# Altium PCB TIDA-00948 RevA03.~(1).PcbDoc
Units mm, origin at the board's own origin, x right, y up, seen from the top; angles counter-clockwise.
Board outline 125.73 x 87.63 mm, 2 copper layers (Top Layer, Bottom Layer), stack 1.575 mm thick; 28 components, 8 nets, 44 pads, 0 vias.
Unrouted connection lines stored in the file: 1.
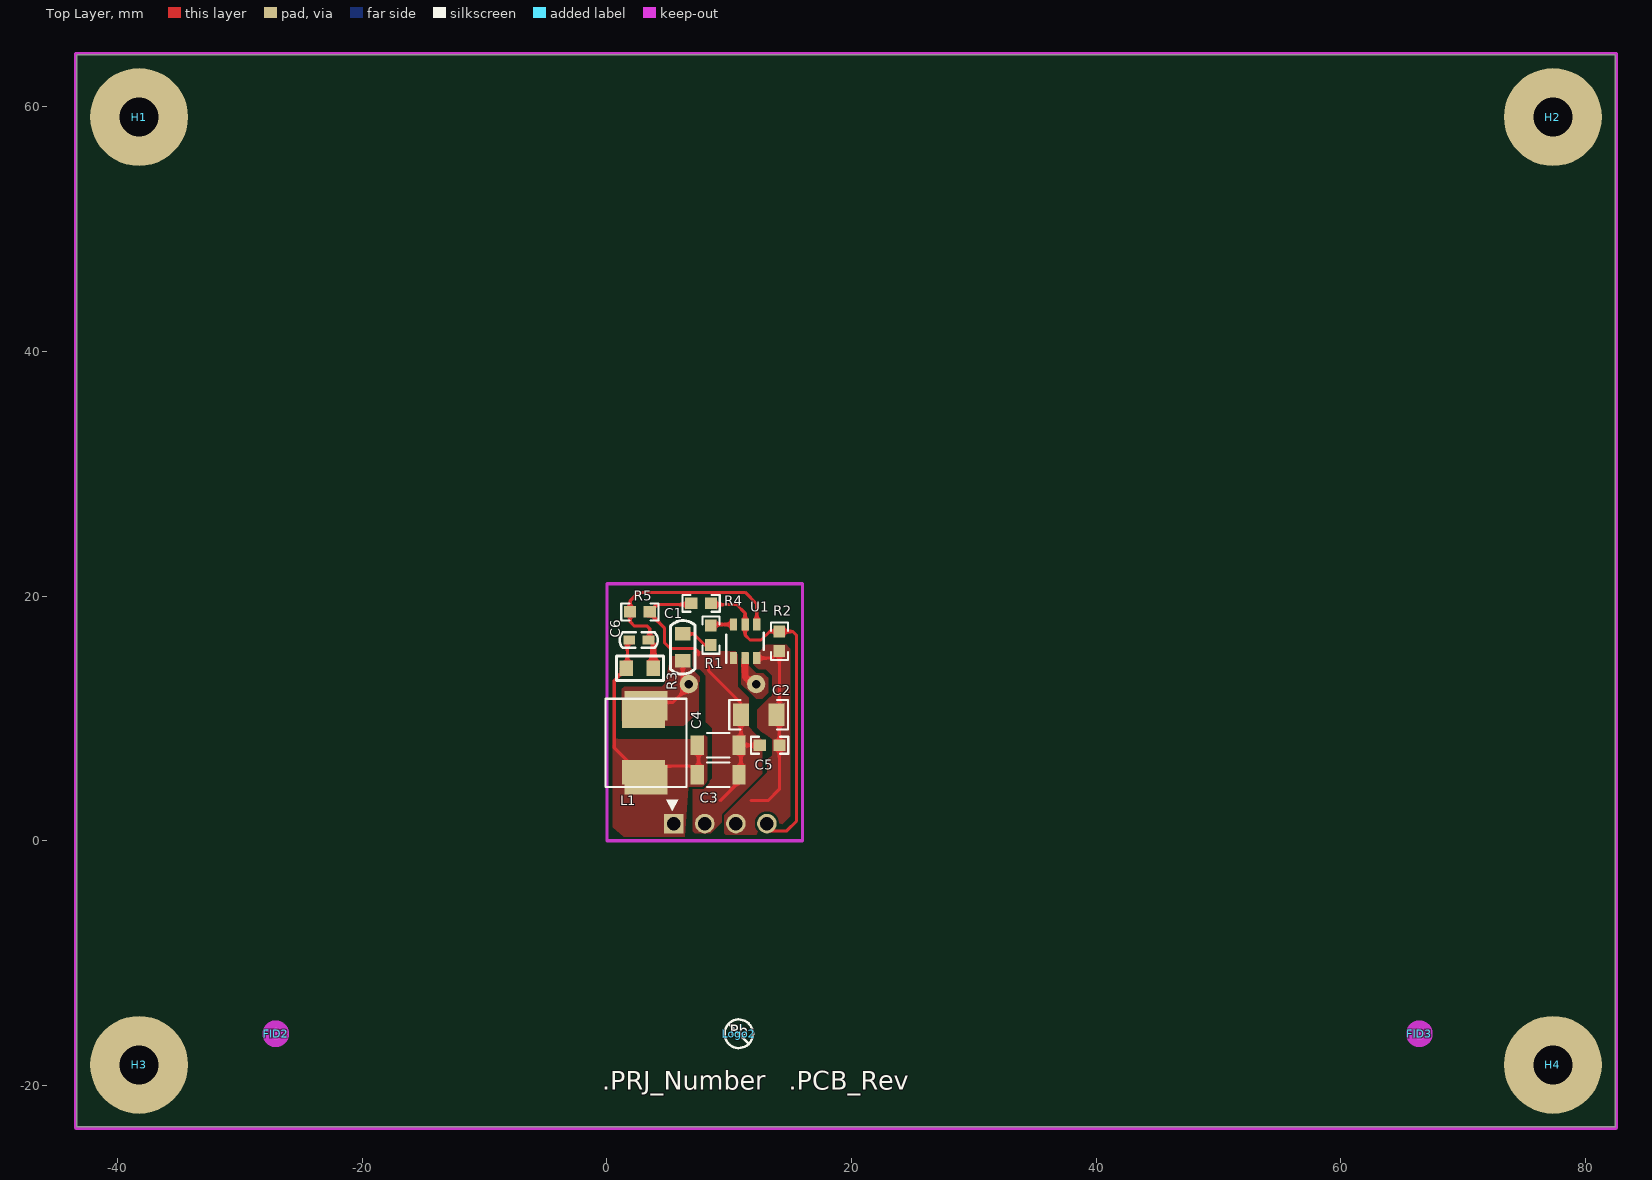
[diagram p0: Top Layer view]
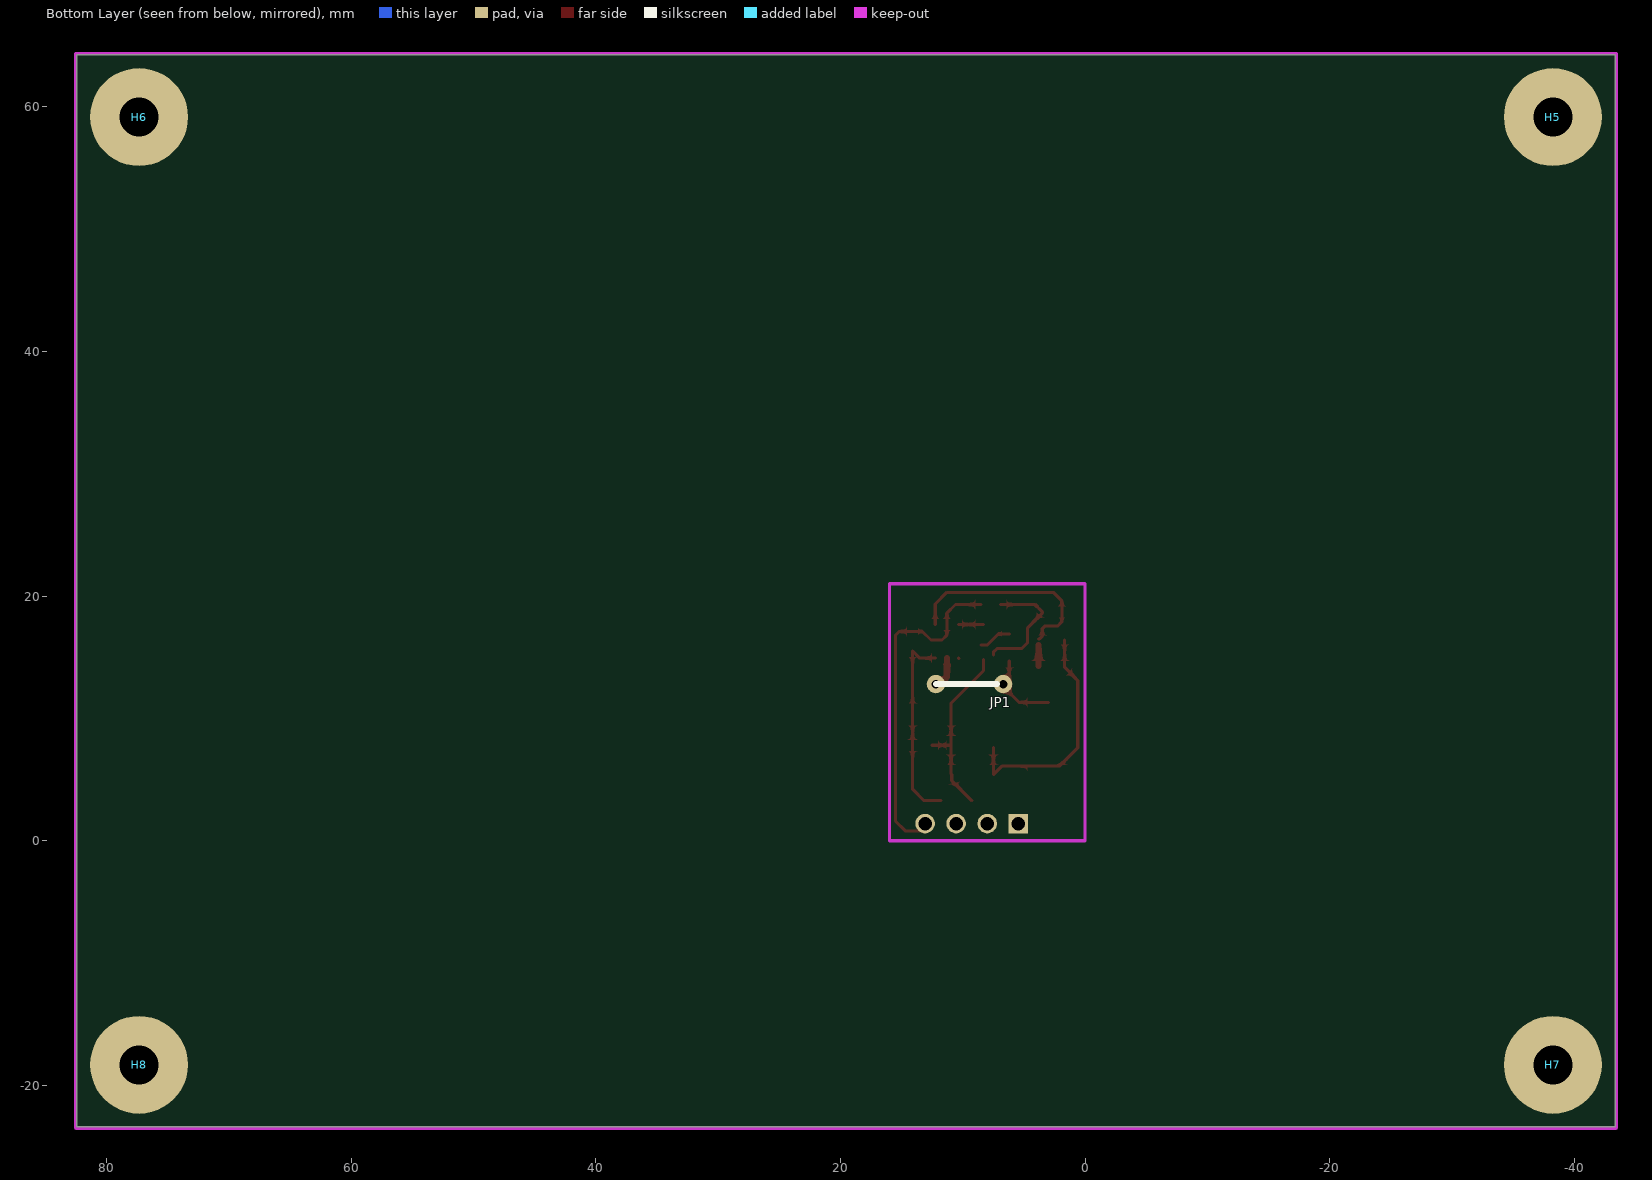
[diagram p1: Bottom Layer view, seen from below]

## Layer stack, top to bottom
Top Solder: solder mask 0.0102, Solder Resist, Dk 3.5
Top Layer: signal copper 0.0356
Dielectric1: core 1.5037, FR-4, Dk 4.8
Bottom Layer: signal copper 0.0356
Bottom Solder: solder mask 0.0102, Solder Resist, Dk 3.5

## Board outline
-43.32,-23.4 82.41,-23.4 82.41,64.23 -43.32,64.23

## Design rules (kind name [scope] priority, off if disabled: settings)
AcuteAngle [All] p1: minimum=4.50000000000000E+0001 checktracksonly=FALSE
AssemblyTestPointUsage [All] p1: valid=2
Clearance Clearance_Keepouts [((IsTrack Or IsArc) And Not InPoly) And IsFree and IsKeepOut vs ((IsTrack Or IsArc) And Not InPoly) And IsFree and IsKeepOut] p1 off: gap=0
Clearance Clearance_BoardEdge_MountingHoles [OnCopper and InComponentClass('Mounting Holes') vs IsKeepOut] p2 off: gap=1.016
Clearance Clearance_BoardEdge_Poly [OnCopper and InPoly vs IsKeepOut] p3 off: gap=0.635
Clearance Clearance_BoardEdge [OnCopper and Not InComponentClass('Logo') and not InComponentClass('FiducialMark') and not InRegion(1000,500,4000,800) and Not IsKeepout vs IsKeepOut] p4 off: gap=1.905
Clearance Clearance_Poly [InPolygon] p5 off: gap=0.635
Clearance [All] p6: gap=0.2
ComponentClearance ComponentClearance_MountingHoles_FiducialMarks [InComponentClass('Mounting Holes') vs InComponentClass('FiducialMark')] p1: gap=1.27 collisioncheckmode=3 verticalgap=0.254 showdistances=FALSE
ComponentClearance ComponentClearance_Shunt [InComponentClass('Header') vs InComponentClass('Shunt')] p2: gap=0 collisioncheckmode=3 verticalgap=0 showdistances=FALSE
ComponentClearance ComponentClearance_Logo [InComponentClass('Logo')] p3: gap=1.27 collisioncheckmode=3 verticalgap=0.254 showdistances=FALSE
ComponentClearance ComponentClearance_ScrewToNut [(HasFootprint('NY PMS 440 0025 PH')) vs (HasFootprint('Keystone_1902C'))] p4: gap=0.127 collisioncheckmode=3 verticalgap=0.254 showdistances=FALSE
ComponentClearance ComponentClearance_MountingHoles [InComponentClass('Mounting Holes')] p5: gap=6.35 collisioncheckmode=3 verticalgap=2540 showdistances=FALSE
ComponentClearance ComponentClearance_SmallPassives [HasFootprint('0201*') or HasFootprint('0402*') or HasFootprint('0508') or HasFootprint('0603*') or HasFootprint('0612') or HasFootprint('0805*') or HasFootprint('0815*') or HasFootprint('0830*') or HasFootprint('1206*') or HasFootprint('1210*') or HasFootprint('1808*') or HasFootprint('1812*') or HasFootprint('1825*') or HasFootprint('2010*') or HasFootprint('2220*') or HasFootprint('2225*') or HasFootprint('2512*') or HasFootprint('2728*') or HasFootprint('3518*') vs HasFootprint('0201*') or HasFootprint('0402*') or HasFootprint('0508') or HasFootprint('0603*') or HasFootprint('0612') or HasFootprint('0805*') or HasFootprint('0815*') or HasFootprint('0830*') or HasFootprint('1206*') or HasFootprint('1210*') or HasFootprint('1808*') or HasFootprint('1812*') or HasFootprint('1825*') or HasFootprint('2010*') or HasFootprint('2220*') or HasFootprint('2225*') or HasFootprint('2512*') or HasFootprint('2728*') or HasFootprint('3518*')] p6: gap=0.508 collisioncheckmode=3 verticalgap=0.254 showdistances=FALSE
ComponentClearance ComponentClearance_THtoSMT [IsThruComponent vs IsSMTComponent] p7: gap=2.54 collisioncheckmode=3 verticalgap=0.762 showdistances=FALSE
ComponentClearance ComponentClearance_THtoTH [IsThruComponent vs IsThruComponent] p8: gap=3 collisioncheckmode=3 verticalgap=0.762 showdistances=FALSE
ComponentClearance [All] p9: gap=1.016 collisioncheckmode=3 verticalgap=0.254 showdistances=FALSE
DiffPairsRouting [All] p1: maxlimit=2.54 minlimit=0.254 mostfreqgap=0.254 toplayer_minwidth=0.381 toplayer_maxwidth=0.381 toplayer_prefwidth=0.381 bottomlayer_minwidth=0.381 bottomlayer_maxwidth=0.381 bottomlayer_prefwidth=0.381 maxuncoupledlength=25.4
FabricationTestPointUsage TestPointUsage [All] p1: valid=2 allowmultiple=FALSE
FabricationTestpoint Testpoint [All] p1: side=3 testpointundercomponent=TRUE minsize=1.016 maxsize=2.54 preferedsize=1.524 minholesize=0 maxholesize=1.016 preferedholesize=0.813 testpointgrid=0.025 allowsidetop=TRUE allowsidebottom=TRUE usegrid=TRUE gridtolerance=0
FanoutControl Fanout_LCC [IsLCC] p1: bgadir=Out bgaviamode=Centered fanoutstyle=Auto fanoutdirection=Alternating viagrid=0.025 // Fanout_LCC (Default Rule)
FanoutControl Fanout_BGA [IsBGA] p2: bgadir=Out bgaviamode=Centered fanoutstyle=Auto fanoutdirection=Alternating viagrid=0.025 // Fanout_BGA (Default Rule)
FanoutControl Fanout_Default [All] p4: bgadir=Out bgaviamode=Centered fanoutstyle=Auto fanoutdirection=Alternating viagrid=0.025 // Fanout_Default (Default Rule)
FanoutControl Fanout_Small [(CompPinCount < 5)] p5: bgadir=Out bgaviamode=Centered fanoutstyle=Auto fanoutdirection=OutThenIn viagrid=0.025 // Fanout_Small (Default Rule)
HoleSize [All] p1: absolutevalues=TRUE maxlimit=6.375 minlimit=0.203 maxpercent=80.000 minpercent=20.000
MinimumAnnularRing MinimumAnnularRing_ThermalPadVias [IsVia and InAnyComponent] p1: minimumring=0.15
MinimumAnnularRing [All] p2: minimumring=0.229
MinimumSolderMaskSliver MinimumSolderMaskSliver_Logo [InComponentClass('Logo') vs InComponentClass('Logo')] p1: minsoldermaskwidth=0.018
MinimumSolderMaskSliver [All] p2: minsoldermaskwidth=0.1
PlaneConnect [All] p1: planeconnectstyle=Relief reliefexpansion=0.254 reliefentries=4 reliefconductorwidth=0.254 reliefairgap=0.254
PolygonConnect [All] p1: connectstyle=Direct reliefconductorwidth=0.254 reliefentries=4 polygonreliefangle="90 Angle" airgapwidth=0.254
RoutingVias ThermalPadVias [IsVia and InAnyComponent] p1: holewidth=0.2 width=0.5 viastyle="Through Hole" minholewidth=0.2 minwidth=0.5 maxholewidth=0.33 maxwidth=0.6
RoutingVias [All] p2: holewidth=0.406 width=0.864 viastyle="Through Hole" minholewidth=0.2 minwidth=0.66 maxholewidth=1.016 maxwidth=1.651
SilkToBoardRegionClearance [Not ((IsComment or IsDesignator) And (Hide <> 'False')) and not InRegion(1000,500,4000,800)] p1:
SilkToSilkClearance SilkToSilkClearance_Pb-FreeLogo [(HasFootprint('Pb-Free_Overlay_Medium') OR HasFootprint('Pb-Free_Overlay_Small')) vs (HasFootprint('Pb-Free_Overlay_Medium') OR HasFootprint('Pb-Free_Overlay_Small'))] p1: silktosilkclearance=0
SilkToSilkClearance [All] p2: silktosilkclearance=0.102
SilkToSolderMaskClearance SilkToComonentPadClearance [IsPad and InAnycomponent] p1: minsilkscreentomaskgap=0.127 clearancetoexposedcopper=TRUE
SilkToSolderMaskClearance "Silk to Solder Mask Opening" [All] p2: minsilkscreentomaskgap=0.102 clearancetoexposedcopper=FALSE
SolderMaskExpansion [All] p1: expansion=0.05
UnpouredPolygon [All] p1: allowunpoured=FALSE
Width [All] p1: maxlimit=2.54 minlimit=0.152 preferedwidth=0.254 checkconnectedcopper=TRUE
14 further rules are at their usual default settings.

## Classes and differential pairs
component class "Mounting Holes": H1 H2 H3 H4
component class TID_Hardware: FID2 FID3 H1 H2 H3 H4 H5 H6 H7 H8 Logo2 ZZ2 ZZ3 ZZ4
component class FiducialMark: FID2 FID3
component class AssemblyNote: ZZ2 ZZ3 ZZ4
component class Header: JP1
component class "TIDA-00948 RevA": C1 C2 C3 C4 C5 C6 JP1 L1 R1 R2 R3 R4 R5 U1

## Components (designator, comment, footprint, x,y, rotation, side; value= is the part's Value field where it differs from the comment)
C1 "GRM188R71E104KA01D" C/0805/SMT1 6.2,16.8 r270 top
C2 "GRM31CR71E106KA12L" 1206 12.4,10.3 r180 top
C3 "GCM31CR71A226KE02" 1206_190 9.1,5.4 r0 top
C4 "GCM31CR71A226KE02" 1206_190 9.1,7.8 r0 top
C5 "GRM188R71E104KA01D" 0603 13.3,7.8 r180 top
C6 "06033C101KAT2A" C/0603 2.6,16.4 r0 top
FID2 "Fiducial" Fiducial10-20 -27.064,-15.78 r0 top
FID3 "Fiducial" Fiducial10-20 66.408,-15.78 r0 top
H1 "NY PMS 440 0025 PH" "NY PMS 440 0025 PH" -38.24,59.15 r0 top locked
H2 "NY PMS 440 0025 PH" "NY PMS 440 0025 PH" 77.33,59.15 r0 top locked
H3 "NY PMS 440 0025 PH" "NY PMS 440 0025 PH" -38.24,-18.32 r0 top locked
H4 "NY PMS 440 0025 PH" "NY PMS 440 0025 PH" 77.33,-18.32 r0 top locked
H5 "1902C" Keystone_1902C -38.24,59.15 r180 bottom locked
H6 "1902C" Keystone_1902C 77.33,59.15 r180 bottom locked
H7 "1902C" Keystone_1902C -38.24,-18.32 r180 bottom locked
H8 "1902C" Keystone_1902C 77.33,-18.32 r180 bottom locked
JP1 "Comment" JUMP-5 7.2,12.8 r0 bottom
L1 "LPS8045B-333MRB" WE-PD-M 3.2,8 r270 top
Logo2 "Pb-Free Symbol" Pb-Free_Overlay_Small 10.782,-15.78 r0 top
R1 "CRCW06030000Z0EA" 0603 8.5,16.8 r270 top
R2 "CRCW0603510KJNEA" 0603 14.1,16.3 r270 top
R3 "CRCW0603100KFKEA" R/0805/SMT1 2.7,14.1 r180 top
R4 "CRCW0603105KFKEA" 0603 7.7,19.4 r0 top
R5 "CRCW060313K3FKEA" 0603 2.7,18.7 r180 top
U1 "TPS54202DDCR" DDC0006A_N 11.3,16.3 r90 top
ZZ2 "These assemblies are ESD sensitive, ESD precautions shall be observed." AssemblyNote -38.621,73.859 r0 top
ZZ3 "These assemblies must be clean and free from flux and all contaminants. Use of no clean flux is not acceptable." AssemblyNote -38.621,71.61 r0 top
ZZ4 "These assemblies must comply with workmanship standards IPC-A-610 Class 2, unless otherwise specified." AssemblyNote -38.621,69.361 r0 top

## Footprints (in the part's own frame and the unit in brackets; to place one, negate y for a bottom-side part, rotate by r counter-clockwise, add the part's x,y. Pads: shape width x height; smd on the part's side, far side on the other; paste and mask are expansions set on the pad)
0603 [mm] "0603 from SM-752 data"
  rect 1x0.95 smd: 1(-0.8,0) 2(0.8,0)
  silkscreen extent -1.52,-0.69 1.52,0.69, body extent -0.87,-0.47 0.87,0.47, height 1
1206 [mm] "1206 from SM-752 data"
  rect 1.3x1.85 smd: 1(-1.45,0) 2(1.45,0)
  silkscreen extent -2.4,-1.21 2.4,1.21, body extent -1.7,-0.9 1.7,0.9, height 1.35
1206_190 [mm] "1206_190"
  rect 1.1x1.6 smd: 1(-1.7,0) 2(1.7,0)
  silkscreen extent -0.9,-1 0.9,1, body extent -1.75,-0.95 1.75,0.95, height 1.9
AssemblyNote [mm] "Assembly Note"
C/0603 [mil]
  rect 38x30 smd: 1(-30.52,0.06) 2(31.48,0.06)
  silkscreen extent -62,-25 62,25
C/0805/SMT1 [mm]
  rect 1.1x1.25 smd: 1(-0.1,0) 2(2.1,0)
  silkscreen extent -1.19,-1 3.19,1.01
DDC0006A_N [mm]
  rrect17% 1x0.6 smd: 1(-1.375,0.95) 2(-1.375,0) 3(-1.375,-0.95) 4(1.375,-0.95) 5(1.375,0) 6(1.375,0.95)
  silkscreen extent -1.75,-1.52 0.7,1.53, body extent -1.43,-1.48 1.43,1.49, height 0.92
Fiducial10-20 [mm]
  round 1 smd mask+0.5: 1(0,0)
  Top Layer keep-out circle w1.178: c0,0 r0.5
JUMP-5 [mm]
  round 1.5 hole 0.7: 1(-0.5,0) 2(5,0)
  silkscreen extent 0,0 5,0
Keystone_1902C [mm] "Hex Standoff, 4-40 threaded, nylon"
  body extent -3.68,-3.2 3.71,3.2, height 12.73
"NY PMS 440 0025 PH" [mm] "4-40 nylon screw and mounting hole"
  round 8 hole 3.2: 1(0,0)
  body extent -3.3,-3.3 3.3,3.3, height 2.69
Pb-Free_Overlay_Small [mm]
  silkscreen extent -1.16,-1.17 1.17,1.17
R/0805/SMT1 [mm]
  rect 1.1x1.25 smd: 1(-1.1,0) 2(1.1,0)
  silkscreen extent -1.92,-1 1.93,1
WE-PD-M [mm] "Wurth Elektronik recommended land pattern, 2008-01-04"
  rect 2.4x3.5 smd: 1(-3.035,0) 2(3.004,0)
  silkscreen extent -3.6,-3.3 3.6,3.3, body extent -3.81,-3.84 3.81,3.79, height 4.5

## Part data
C1 C5: "CAP, CERM, 0.1 μF, 25 V, +/- 10%, X7R, 0603"
C2: "CAP, CERM, 10 μF, 25 V, +/- 10%, X7R, 1206"
C3 C4: "CAP, CERM, 22 μF, 10 V, +/- 10%, X7R, AEC-Q200 Grade 1, 1206_190"
C6: "CAP, CERM, 100 pF, 25 V, +/- 10%, X7R, 0603"
FID2 FID3: "Fiducial mark.  There is nothing to buy or mount."
H1 H2 H3 H4: "Machine Screw, Round, #4-40 x 1/4, Nylon, Philips panhead"
H5 H6 H7 H8: "Standoff, Hex, 0.5\"L #4-40 Nylon"
L1: "Inductor, Shielded, Ferrite, 33 μH, 1.2 A, 0.121 ohm, SMD"
Logo2: library part Pb-Free
R1: "RES, 0, 5%, 0.1 W, 0603"
R2: "RES, 510 k, 5%, 0.1 W, 0603"
R3: "RES, 100 k, 1%, 0.1 W, 0603"
R4: "RES, 105 k, 1%, 0.1 W, 0603"
R5: "RES, 13.3 k, 1%, 0.1 W, 0603"
U1: "4.5-V TO 28-V INPUT, 2-A OUTPUT, EMI FRIENDLY SYNCHRONUOUS STEP-DOWN CONVERTOR, DDC0006A"
ZZ2 ZZ3 ZZ4: library part AssemblyNote

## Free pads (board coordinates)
  rect 3.5x2 smd: 0(3,5.6)
  rect 3.5x2.4 smd: 0(3,10.4)
  rect 1.6x1.6 hole 1.1: 0(5.46,1.4)
  round 1.6 hole 1.1: 0(8,1.4) 0(10.54,1.4) 0(13.08,1.4)

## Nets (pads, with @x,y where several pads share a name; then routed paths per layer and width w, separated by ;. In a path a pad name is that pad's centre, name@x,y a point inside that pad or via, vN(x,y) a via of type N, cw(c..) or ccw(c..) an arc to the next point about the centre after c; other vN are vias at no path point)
+5V: C3.1 C4.1 C6.1 L1.2 pad.0@3,5.6 pad.0@5.46,1.4 R3.2 | length 19.3
  Top Layer w0.254: C6.1@1.678,16.401 1.678,14.178 0.6,13.1 0.6,7.6 2.104,6.097 6.804,6.097 7.5,5.4 C4.1@7.5,7.6
EN: pad.0@13.08,1.4 R2.1 R4.2 U1.5 | length 28.5
  Top Layer w0.254: R4.2@8.5,19.3 10.6,19.3 11.3,18.6 U1.5 11.3,16.8 11.7,16.4 12.6,16.4 13.3,17.1 R2.1 15.2,17.1 15.5,16.8 15.5,1.6 14.7,0.8 pad.0@13.08,0.8 ; pad.0@13.08,1.4 13.68,0.8
GND: C2.2 C3.2 C4.2 C5.2 pad.0@8,1.4 R4.1 R5.1 U1.1 | length 24.8
  Top Layer w0.254: R4.1@6.9,19.3 4.1,19.3 R5.1 3.5,18.6 4.7,17.4 4.7,16.2 5.2,15.7 7.2,15.7 7.5,15.4 7.5,15.2 ; 8.3,14.8 8.3,13.9 10.95,11.25 C2.2 C4.2@10.95,7.8 ; 9.258,3.27 10.9,4.912 C3.2@10.9,5.4 ; U1.1@10.325,14.9 U1.1 ; C3.2@10.95,5.45 C4.2@10.95,7.8 ; C5.2 C4.2@10.95,7.8
NetC1_1: C1.1 R1.2 | length 2.7
  Top Layer w0.254: C1.1 7.1,16.9 8,16 R1.2
NetC1_2: C1.2 JP1.1 JP1.2 L1.1 pad.0@3,10.4 U1.2 | length 8.3
  Top Layer w0.254: pad.0@3,11.304 5.403,11.304 JP1.1@6.9,12.8 ; JP1.1@6.2,13.3 C1.2
  Top Layer w0.5: U1.2 11.3,13.4 JP1.2@11.9,12.8
NetC6_2: C6.2 R3.1 R5.2 U1.4 | length 18.9
  Top Layer w0.254: C6.2@3.8,16.5 3.722,16.5 3.5,16.722 3.5,17.338 3.3,17.538 2.262,17.538 1.9,17.9 R5.2 1.9,19.6 2.6,20.3 11.3,20.3 12.25,19.35 U1.4
  Top Layer w0.5: R3.1@3.8,14.3 3.8,16
NetR1_1: R1.1 U1.6 | length 2
  Top Layer w0.254: R1.1@8.325,17.675 U1.6
VIN: C2.1 C5.1 pad.0@10.54,1.4 R2.2 U1.3 | length 16.1
  Top Layer w0.254: 11.798,3.27 13.17,3.27 14.1,4.2 C5.1 R2.2 13.525,14.925 U1.3
pads on no net: FID2.1 FID3.1 H1.1 H2.1 H3.1 H4.1

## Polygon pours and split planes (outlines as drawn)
+5V on Top Layer "Top Layer-No Net 4" (solid, remove dead copper, pour order 10): 8.2,8.7 8.2,4.8 7.8,4.4 6.7,4.4 6.632,4.332 6.3,-0.58 2.857,-0.992 0.5,1.1 0.5,7.8 0.6,7.9 0.6,8.6 0.9,8.3 6.9,8.3
NetC1_2 on Top Layer "Top Layer-No Net 3" (solid, remove dead copper, pour order 8): 11.5,14.9 11.5,14.4 11.8,14.1 12.2,13.7 12.6,13.7 12.8,13.7 13,13.5 13.2,13.3 13.2,12.7 13.2,12.1 12.9,11.8 12.7,11.6 12.3,11.6 12.2,11.6 11.7,12.1 11,12.8 11,14 11,14.9
NetC1_2 on Top Layer "Top Layer-No Net 2" (solid, remove dead copper, pour order 6): 7.5,13 7.5,10.6 7,10.1 6.3,9.4 2.5,9.4 1.6,9.4 1.2,9.8 1.2,12.4 1.4,12.6 3.8,12.6 4.5,12.6 4.78,12.88 5.223,15.094 5.906,15.094 7.6,13.4 7.6,12.4
VIN on Top Layer "Top Layer-No Net 1" (solid, remove dead copper, pour order 4): 12,15.1 12,14.4 12.3,14.1 12.4,14 12.9,14 13,14 13.4,13.6 13.5,13.5 13.5,12.4 13.5,11.9 13.2,11.6 12.3,10.7 12.3,10 12.3,9.223 12.611,8.912 13.015,8.679 13.5,8.3 13.5,7.8 13.5,7 13.1,6.6 13.1,5.6 9.6,2.1 9.6,0.6 9.7,0.5 13.5,0.5 15,2 15,8.3 15,15.7 14.8,15.9 14.7,16 13.6,16 13,16 12.4,15.4
GND on Top Layer "Top Layer-No Net" (solid, remove dead copper, pour order 2): 10.535,15.397 10.7,15.232 10.7,12.8 10.7,12.6 11.2,12.1 11.6,11.7 11.6,10.8 11.6,9.3 12.1,8.8 12.7,8.2 12.7,6.2 12.7,4.8 8.5,0.6 7,0.6 7,4.6 8.033,4.6 8.6,5.087 8.6,9.2 8.3,9.5 8.1,9.7 8.1,13.2 8.1,13.5 7.8,13.8 7.6,14 6.4,14 5.5,14 5.1,14.4 5.1,15.2 5.372,15.472 10.535,15.472

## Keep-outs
Keep-Out Layer:
  lines w0.254: -43.447,-23.4 ccw(c-43.32,-23.4) -43.32,-23.527 ; -43.447,-23.4 ccw(c-43.32,-23.4) -43.32,-23.527 ; -43.447,-23.4 -43.447,64.23 ; -43.447,64.23 cw(c-43.32,64.23) -43.32,64.357 ; -43.447,64.23 cw(c-43.32,64.23) -43.32,64.357 ; -43.32,-23.527 82.41,-23.527 ; -43.32,64.357 82.41,64.357 ; 82.41,-23.527 ccw(c82.41,-23.4) 82.537,-23.4 ; 82.41,-23.527 ccw(c82.41,-23.4) 82.537,-23.4 ; 82.41,64.357 cw(c82.41,64.23) 82.537,64.23 ; 82.41,64.357 cw(c82.41,64.23) 82.537,64.23 ; 82.537,-23.4 82.537,64.23 ; 0,0 16,0 16,21 0,21 0,0
  text ".Layer_Name" at -28.664,-45.206 h1.52

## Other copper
Top Layer:
  text ".Layer_Name" at -28.664,-45.206 h1.52
Bottom Layer:
  text ".Layer_Name" at -28.664,-45.206 h1.52

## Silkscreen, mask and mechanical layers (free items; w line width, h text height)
Top Overlay:
  region: 5.35,2.45 5.85,3.35 4.85,3.35
  text ".PRJ_Number" at -0.394,-20.352 h1.52
  text ".PCB_Rev" at 14.846,-20.352 h1.52
  text ".Layer_Name" at -28.664,-45.206 h1.52
Bottom Overlay:
  text ".Layer_Name" at -28.664,-45.206 h1.52
Top Paste:
  text ".Layer_Name" at -28.664,-45.206 h1.52
Bottom Paste:
  text ".Layer_Name" at -28.664,-45.206 h1.52
Top Solder:
  lines w1: 8.6,12.1 8.6,13.5 ; 9.1,9.6 9.1,11 ; 9.8,12.1 9.8,13.7 ; 10.9,2.27 11.9,3.27 ; 13.1,3.34 13.1,4.6 ; 14.2,12.5 14.2,14.2 ; 14.3,2.1 14.3,3.4 ; 14.5,4.7 14.5,6.3
  text ".Layer_Name" at -28.664,-45.206 h1.52
  text ".Layer_Name" at -28.664,-45.206 h1.52
Bottom Solder:
  text ".Layer_Name" at -28.664,-45.206 h1.52
Drill Guide:
  text ".Layer_Name" at -28.664,-45.206 h1.52
M1 Board Outline:
  the board outline again, w0.254
  text ".Layer_Name" at -28.664,-45.206 h1.52
M2 Board Dimensions:
  rectangle: -43.32,-30.385 -40.145,-27.21
  rectangle: -40.145,-33.56 -30.62,-30.385
  lines w0.178: -43.32,-30.385 -17.92,-30.385 ; -40.145,-33.56 -40.145,-27.21 ; -36.97,-33.56 -36.97,-27.21 ; -30.62,-33.56 -30.62,-27.21 ; -24.27,-33.56 -24.27,-27.21 ; -43.32,-33.56 -17.92,-33.56 -17.92,-27.21 -43.32,-27.21 -43.32,-33.56
  text ".Layer_Name" at -28.664,-45.206 h1.52
M3 3D STEP Top:
  text ".Layer_Name" at -28.664,-45.206 h1.52
M4 3D STEP Bottom:
  text ".Layer_Name" at -28.664,-45.206 h1.52
M5 Assembly Top:
  lines w0.254: -50.737,-47.026 116.903,-47.026 ; -50.737,-41.862 116.954,-41.862 ; -50.737,-36.697 -50.737,-52.191 50.99,-52.191 116.954,-52.191 116.954,-36.697 -50.724,-36.697 -50.724,-52.191 -10.706,-52.191 ; 11.874,-52.191 11.874,-36.697 ; 44.056,-41.862 44.056,-36.697 ; 65.392,-41.862 65.392,-36.697 ; 81.191,-52.356 81.191,-47.204
  text "COMPONENTS MARKED 'DNP' SHOULD NOT BE POPULATED." at -14.021,-31.49 h1.52
  text "ASSEMBLY VARIANT:" at -14.034,-34.424 h1.52
  text ".VariantName" at 12.281,-34.424 h1.52
  text "PCB VIEWED FROM TOP SIDE" at -49.124,-40.054 h1.52
  text "BOARD #:" at 13.779,-40.054 h1.52
  text ".PRJ_Number" at 27.635,-40.054 h1.52
  text "REV:" at 49.085,-40.054 h1.52
  text ".PCB_Rev" at 56.489,-40.054 h1.52
  text "SVN REV:" at 70.37,-40.054 h1.52
  text ".VersionControl_RevNumber" at 83.223,-40.054 h1.52
  text "TID #:" at 13.779,-45.219 h1.52
  text ".TID" at 27.635,-45.219 h1.52
  text "PLOT NAME =" at -49.124,-50.434 h1.52
  text ".plot_File_Name" at -28.664,-50.434 h1.52
  text "GENERATED    :" at 13.83,-50.434 h1.52
  text ".Print_Date" at 35.915,-50.434 h1.52
  text ".Print_Time" at 54.432,-50.434 h1.52
  text "TEXAS INSTRUMENTS" at 86.55,-50.434 h1.52
M6 Assembly Bottom:
  lines w0.254: -50.749,-41.874 116.941,-41.874 ; -50.699,-47.039 116.941,-47.039 ; -14.986,-52.369 -14.986,-47.217 ; 0.813,-41.874 0.813,-36.71 ; 22.149,-41.874 22.149,-36.71 ; 54.33,-52.204 54.33,-36.71 ; 76.911,-52.204 116.929,-52.204 116.929,-36.71 -50.749,-36.71 -50.749,-52.204 15.214,-52.204 116.941,-52.204 116.941,-36.71
  text "COMPONENTS MARKED 'DNP' SHOULD NOT BE POPULATED." at 111.671,-31.477 h1.52
  text ".VariantName" at 85.153,-34.424 h1.52
  text "ASSEMBLY VARIANT:" at 111.544,-34.424 h1.52
  text ".VersionControl_RevNumber" at -17.018,-40.067 h1.52
  text "SVN REV:" at -4.166,-40.067 h1.52
  text ".PCB_Rev" at 9.715,-40.067 h1.52
  text "REV:" at 17.119,-40.067 h1.52
  text ".PRJ_Number" at 38.57,-40.067 h1.52
  text "BOARD #:" at 52.425,-40.067 h1.52
  text "PCB VIEWED FROM BOTTOM SIDE" at 115.328,-40.067 h1.52
  text ".TID" at 38.57,-45.231 h1.52
  text "TID #:" at 52.425,-45.231 h1.52
  text "TEXAS INSTRUMENTS" at -20.346,-50.447 h1.52
  text ".Print_Time" at 11.773,-50.447 h1.52
  text ".Print_Date" at 30.289,-50.447 h1.52
  text "GENERATED    :" at 52.375,-50.447 h1.52
  text ".plot_File_Name" at 94.869,-50.447 h1.52
  text "PLOT NAME =" at 115.328,-50.447 h1.52
M9 Title Sheet:
  drawing of 57 lines, arcs and shapes, not listed
  text "1" at -24.528,180.727 h1.78
  text "2" at 38.862,180.727 h1.78
  text "3" at 102.091,180.727 h1.78
  text "4" at 165.76,180.727 h1.78
  text "5" at 229.235,180.727 h1.78
  text "6" at 292.862,180.727 h1.78
  text "A" at -53.899,151.695 h1.78
  text "A" at 322.021,151.695 h1.78
  text "B" at -53.899,91.243 h1.78
  text "B" at 322.021,91.243 h1.78
  text "C" at -53.899,30.918 h1.78
  text "C" at 322.021,30.918 h1.78
  text "PROJECT TITLE:" at 244.805,-16.351 h1.14
  text ".PRJ_Title" at 246.075,-19.738 h1.78
  text "DESIGNED FOR:" at 244.805,-23.997 h1.14
  text ".PRJ_Customer" at 246.075,-27.553 h1.78
  text "D" at -53.899,-29.28 h1.78
  text "D" at 322.021,-29.28 h1.78
  text "FILE NAME:" at 244.805,-31.617 h1.14
  text ".PCB_File_Name_No_Path" at 246.075,-34.665 h1.78
  text "Texas Instruments (TI) and/or its licensors do not warrant the accuracy or completeness of this specification" at 118.58,-38.776 h1.14
  text "ENGINEER:" at 244.805,-38.983 h1.14
  text "LAYOUT BY:" at 283.032,-38.983 h1.14
  text "or any information contained therein. TI and/or its licensors do not warrant that this design will meet" at 117.437,-41.637 h1.14
  text ".PRJ_Engineer" at 246.075,-42.92 h1.78
  text ".PCB_Layout" at 284.315,-42.92 h1.78
  text "the specifications, will be suitable for your application or fit for any particular purpose, or will operate in" at 117.437,-44.499 h1.14
  text ".Layer_Name" at -28.664,-45.206 h1.52
  text "ALTIUM DESIGNER VERSION:" at 283.032,-46.857 h1.14
  text "an implementation. TI and/or its licensors do not warrant that the design is production worthy. You should" at 117.437,-47.361 h1.14
  text "completely validate and test your design implementation to confirm the system functionality for your application." at 118.58,-50.222 h1.14
  text ".print_Scale" at 246.075,-50.243 h1.78
  text ".Application_BuildNumber" at 284.315,-50.243 h1.78
  text "1" at -24.528,-55.493 h1.78
  text "2" at 38.862,-55.493 h1.78
  text "3" at 102.091,-55.493 h1.78
  text "4" at 165.76,-55.493 h1.78
  text "5" at 229.235,-55.493 h1.78
  text "6" at 292.862,-55.493 h1.78
M10 Fab Notes:
  drawing of 173 lines, arcs and shapes, not listed
  text "DESIGN INFORMATION" at 271.056,134.105 h1.52
  text "MIN. TRACK WIDTH:" at 254.684,129.533 h1.52
  text "8" at 282.529,129.533 h1.52
  text "MIL" at 286.46,129.533 h1.52
  text "MIN. CLEARANCE:" at 254.684,126.181 h1.52
  text "0.2" at 281.005,126.181 h1.52
  text "mm" at 286.46,126.181 h1.52
  text "MIN. VIA PAD SIZE:" at 254.684,122.828 h1.52
  text "24" at 281.767,122.828 h1.52
  text "MIL" at 286.46,122.828 h1.52
  text "0.05mm (2MIL)" at 272.337,119.228 h1.52
  text "MINIMUM ANNULAR RING" at 246.322,119.12 h1.52
  text "EXTERNAL" at 290.321,119.12 h1.52
  text "PER" at 251.402,116.122 h1.52
  text "IPC-D-275 CLASS 2 LEVEL C" at 256.99,116.122 h1.52
  text "MIL, HOLES" at 294.791,113.27 h1.52
  text "+/-" at 284.823,113.252 h1.52
  text "+/-" at 306.514,113.252 h1.52
  text "REGISTRATION TOLERANCES:" at 246.322,113.125 h1.52
  text "METAL" at 276.796,113.125 h1.52
  text "5" at 291.432,113.125 h1.52
  text "3" at 312.59,113.125 h1.52
  text "MIL" at 315.543,113.125 h1.52
  text "+/-" at 306.514,110.255 h1.52
  text "HOLE SIZE TOLERANCE (UNLESS OTHERWISE SPECIFIED):" at 246.322,110.128 h1.52
  text "3" at 312.59,110.128 h1.52
  text "MIL" at 315.543,110.128 h1.52
  text "MATERIAL:" at 244.423,104.808 h1.52
  text "FR-4 High Tg" at 269.479,101.243 h1.52
  text "FR-408" at 255.116,101.025 h1.52
  text "OTHER" at 292.911,101.025 h1.52
  text "X" at 265.544,100.933 h1.52
  text "62 MIL (1.6mm) +/-10%" at 263.247,96.892 h1.52
  text "THICKNESS:" at 246.322,96.784 h1.52
  text "X" at 259.991,96.784 h1.52
  text "OTHER" at 295.883,96.784 h1.52
  text "TOLERANCE:" at 246.322,92.77 h1.52
  text "X" at 267.64,92.77 h1.52
  text "ANSI IPC-6012 TYPE 3 CLASS 2" at 272.389,92.77 h1.52
  text "OTHER +/-" at 272.388,88.808 h1.52
  text "BOW & TWIST:" at 246.322,84.82 h1.52
  text "X" at 267.64,84.82 h1.52
  text "ANSI IPC-6012 TYPE 3 CLASS 2" at 272.389,84.82 h1.52
  text "OTHER +/-" at 272.388,80.794 h1.52
  text "DRILLING:" at 244.423,77.276 h1.52
  text "REFERENCE:" at 246.322,74.305 h1.52
  text "X" at 262.787,74.305 h1.52
  text "AS SHOWN" at 267.537,74.305 h1.52
  text "X" at 285.672,74.305 h1.52
  text "NC_DRILL FILES" at 289.152,74.305 h1.52
  text "PTH MIN COPPER THICKNESS:" at 246.322,70.291 h1.52
  text "X" at 280.618,70.291 h1.52
  text "1MIL" at 284.098,70.291 h1.52
  text "OTHER" at 296.721,70.291 h1.52
  text "BOARD FINISH:" at 244.423,66.253 h1.52
  text "SILKSCREEN:" at 248.366,63.256 h1.52
  text "X" at 272.464,63.256 h1.52
  text "TOP" at 275.665,63.256 h1.52
  text "X" at 285.418,63.256 h1.52
  text "BOTTOM" at 288.644,63.256 h1.52
  text "SILKSCREEN COLOR:" at 248.366,59.014 h1.52
  text "X" at 272.438,59.014 h1.52
  text "WHITE" at 275.665,59.014 h1.52
  text "OTHER" at 288.644,59.014 h1.52
  text "X" at 275.766,54.97 h1.52
  text "GREEN" at 278.992,54.97 h1.52
  text "OTHER" at 294.689,54.97 h1.52
  text "SOLDER RESIST COLOR:" at 248.366,54.696 h1.52
  text "X" at 275.766,50.652 h1.52
  text "MATTE" at 278.992,50.652 h1.52
  text "SEMI-GLOSS" at 294.678,50.636 h1.52
  text "IMMERSION GOLD (ENIG)" at 271.372,45.864 h1.52
  text "ENEPIG" at 305.346,45.78 h1.52
  text "SURFACE FINISH:" at 244.423,45.755 h1.52
  text "X" at 266.624,45.755 h1.52
  text "IMM. TIN/SILVER OR EQUIV" at 252.793,41.767 h1.52
  text "OTHER" at 289.152,41.767 h1.52
  text "ARRAY/PANEL:" at 244.423,37.221 h1.52
  text "CUT AND TRIM PER M1 BOARD OUTLINE" at 271.372,37.112 h1.52
  text "N.C. ROUTE" at 271.372,33.258 h1.52
  text "X" at 288.619,33.258 h1.52
  text "V. SCORE" at 293.369,33.258 h1.52
  text "CERTIFICATION:" at 244.423,29.778 h1.52
  text "MATERIALS AND WORKMANSHIP FOR ALL PCBS" at 262.838,29.778 h1.52
  text "TO MEET OR EXCEED THE REQUIREMENTS OF:" at 262.838,27.289 h1.52
  text "X" at 253.351,23.822 h1.52
  text "ANSI IPC-A-600F CLASS ->" at 256.882,23.822 h1.52
  text "X" at 298.514,23.822 h1.52
  text "2" at 301.535,23.822 h1.52
  text "1" at 293.534,23.784 h1.52
  text "3" at 310.526,23.784 h1.52
  text "X" at 274.028,19.771 h1.52
  text "RoHS" at 277.506,19.771 h1.52
  text "OTHER" at 293.874,19.771 h1.52
  text "PER ORDER" at 303.96,19.771 h1.52
  text "ALL BOARDS MUST MEET OR EXCEED UL94-V0 REQUIREMENTS." at 245.122,15.564 h1.52
  text "PCB MUST BEAR THE UL94V-0 UL REGISTERED MATERIAL ID NUMBER" at 245.122,12.516 h1.52
  text "ADDITIONAL REQUIREMENTS:" at 244.423,8.112 h1.52
  text "MICROSECTION:" at 246.322,5.191 h1.52
  text "YES" at 269.328,5.191 h1.52
  text "REQUIRED" at 291.21,1.225 h1.52
  text "BARE BOARD ELEC. TEST:" at 246.322,1.153 h1.52
  text "NONE" at 279.488,1.153 h1.52
  text "X" at 287.984,1.153 h1.52
  text "PER ORDER" at 306.246,1.153 h1.52
  text ".Layer_Name" at -28.664,-45.206 h1.52
M11 Gerber Information:
  lines w0.254: -50.737,-47.026 116.903,-47.026 ; -50.737,-41.862 116.954,-41.862 ; -50.737,-36.697 -50.737,-52.191 50.99,-52.191 116.954,-52.191 116.954,-36.697 -50.724,-36.697 -50.724,-52.191 -10.706,-52.191 ; 11.874,-52.191 11.874,-36.697 ; 44.056,-41.862 44.056,-36.697 ; 65.392,-41.862 65.392,-36.697 ; 81.191,-52.356 81.191,-47.204
  text "ALL ARTWORK VIEWED FROM TOP SIDE" at -49.124,-40.054 h1.52
  text "BOARD #:" at 13.779,-40.054 h1.52
  text ".PRJ_Number" at 27.635,-40.054 h1.52
  text "REV:" at 49.085,-40.054 h1.52
  text ".PCB_Rev" at 56.489,-40.054 h1.52
  text "SVN REV:" at 70.37,-40.054 h1.52
  text ".VersionControl_RevNumber" at 83.223,-40.054 h1.52
  text "LAYER NAME =" at -49.124,-45.206 h1.52
  text "TID #:" at 13.779,-45.219 h1.52
  text ".TID" at 27.635,-45.219 h1.52
  text "PLOT NAME =" at -49.124,-50.434 h1.52
  text ".plot_File_Name" at -28.664,-50.434 h1.52
  text "GENERATED    :" at 13.83,-50.434 h1.52
  text ".Print_Date" at 35.915,-50.434 h1.52
  text ".Print_Time" at 54.432,-50.434 h1.52
  text "TEXAS INSTRUMENTS" at 86.55,-50.434 h1.52
M12 Stackup:
  drawing of 191 lines, arcs and shapes, not listed
  text "Layer" at 205.361,175.482 h1.52
  text "Name" at 215.772,175.482 h1.52
  text "Material" at 239.388,175.482 h1.52
  text "Thickness" at 261.226,175.482 h1.52
  text "Constant" at 277.732,175.482 h1.52
  text "Board Layer Stack" at 292.206,175.482 h1.52
  text "1" at 205.361,172.434 h1.52
  text "Top Overlay" at 215.772,172.434 h1.52
  text "2" at 205.361,169.386 h1.52
  text "Top Solder" at 215.772,169.386 h1.52
  text "Solder Resist" at 239.388,169.386 h1.52
  text "0.40mil" at 261.226,169.386 h1.52
  text "3.5" at 277.732,169.386 h1.52
  text "3" at 205.361,166.338 h1.52
  text "Top Layer" at 215.772,166.338 h1.52
  text "Copper" at 239.388,166.338 h1.52
  text "1.40mil" at 261.226,166.338 h1.52
  text "4" at 205.361,163.29 h1.52
  text "Dielectric1" at 215.772,163.29 h1.52
  text "FR-4" at 239.388,163.29 h1.52
  text "59.20mil" at 261.226,163.29 h1.52
  text "4.8" at 277.732,163.29 h1.52
  text "5" at 205.361,160.242 h1.52
  text "Bottom Layer" at 215.772,160.242 h1.52
  text "Copper" at 239.388,160.242 h1.52
  text "1.40mil" at 261.226,160.242 h1.52
  text "6" at 205.361,157.194 h1.52
  text "Bottom Solder" at 215.772,157.194 h1.52
  text "Solder Resist" at 239.388,157.194 h1.52
  text "0.40mil" at 261.226,157.194 h1.52
  text "3.5" at 277.732,157.194 h1.52
  text "7" at 205.361,154.146 h1.52
  text "Bottom Overlay" at 215.772,154.146 h1.52
  text ".Layer_Name" at -28.664,-45.206 h1.52
M13 Component Bodies Top:
  text ".Layer_Name" at -28.664,-45.206 h1.52
M14 Component Bodies Bottom:
  text ".Layer_Name" at -28.664,-45.206 h1.52
M15 Courtyards Top:
  text ".Layer_Name" at -28.664,-45.206 h1.52
M16 Courtyards Bottom:
  text ".Layer_Name" at -28.664,-45.206 h1.52
Drill Drawing:
  circle w0.025: c98.229,54.613 r0.633
  lines w0.025: 97.596,50.184 98.862,50.184 98.862,51.449 97.596,51.449 97.596,50.184 ; 97.596,59.042 98.862,59.042 98.229,57.776 97.596,59.042
  lines w0.305: 95.872,49.045 149.705,49.045 ; 95.872,60.434 149.705,60.434 ; 105.287,45.249 105.287,64.23 ; 114.358,45.249 114.358,64.23 ; 131.173,45.249 131.173,64.23 ; 138.395,45.249 138.395,64.23 ; 95.872,45.249 149.705,45.249 149.705,64.23 95.872,64.23 95.872,45.249
  text "Symbol" at 98.15,61.573 h1.83
  text "Quantity" at 106.426,61.573 h1.83
  text "Finished Hole Size" at 115.497,61.573 h1.83
  text "Plated" at 132.311,61.573 h1.83
  text "Hole Type" at 139.534,61.573 h1.83
  text "2" at 106.426,57.776 h1.52
  text "27.56mil (0.700mm)" at 115.497,57.776 h1.52
  text "PTH" at 132.311,57.776 h1.52
  text "Round" at 139.534,57.776 h1.52
  text "4" at 106.426,53.98 h1.52
  text "43.31mil (1.100mm)" at 115.497,53.98 h1.52
  text "PTH" at 132.311,53.98 h1.52
  text "Round" at 139.534,53.98 h1.52
  text "4" at 106.426,50.184 h1.52
  text "125.98mil (3.200mm)" at 115.497,50.184 h1.52
  text "PTH" at 132.311,50.184 h1.52
  text "Round" at 139.534,50.184 h1.52
  text "10 Total" at 106.426,46.388 h1.52
  text ".Layer_Name" at -28.664,-45.206 h1.52

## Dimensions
-43.32,-33.56 to -17.92,-33.56 on M2 Board Dimensions
-43.32,-23.4 to -43.32,64.23 on M2 Board Dimensions
-43.32,-23.4 to 82.41,-23.4 on M2 Board Dimensions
